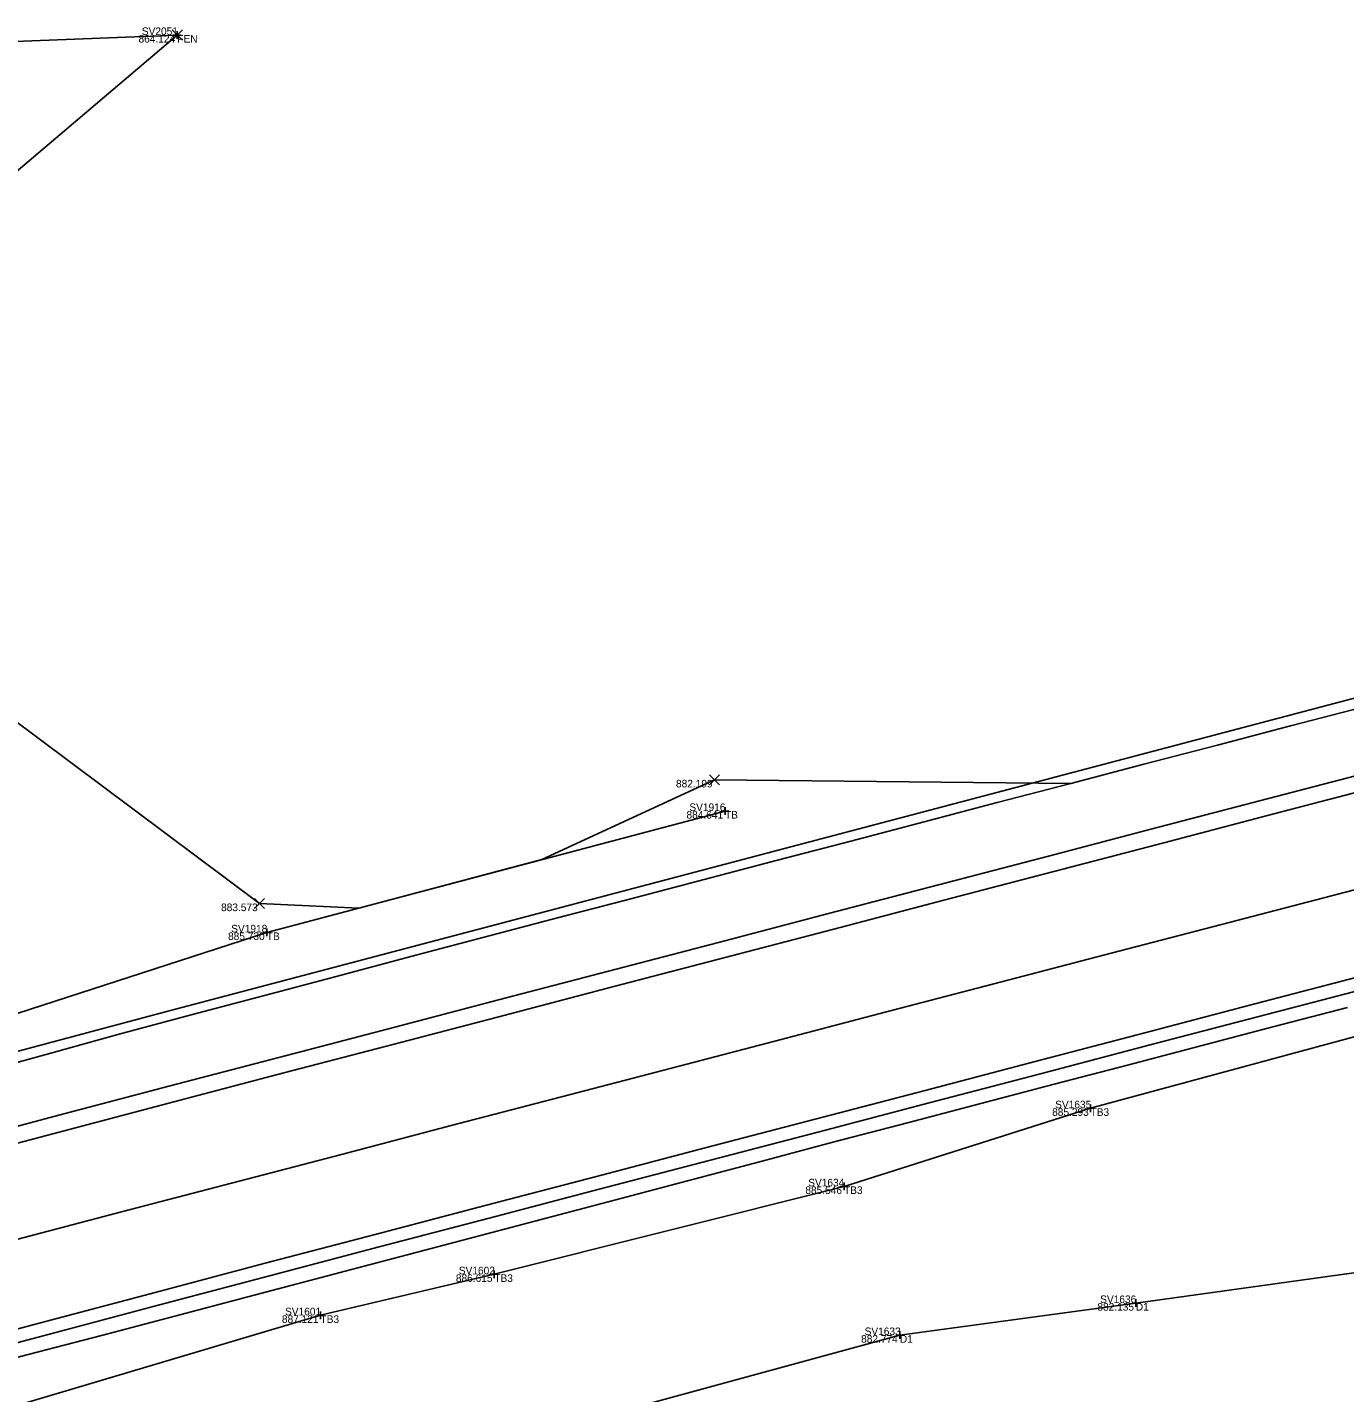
# Model space of a CAD drawing. Extents: x 2125299 to 2129212, y 713100 to 714300.
# Drawn here: x 2127665 to 2127838.8, y 713888.4 to 714068.6 of the extents above; entities that cross this region are included whole.
import ezdxf

# ---------------------------------------------------------------- set-up
doc = ezdxf.new("R2010")
doc.units = 0
for name, color, linetype in [('_CIVIL_CONSTRUCTION', 7, 'Continuous'), ('DR_X_Ditch', 7, 'Continuous'), ('DT_X_Terrain_Boundary', 7, 'Continuous'), ('PV_X_EOP', 7, 'Continuous'), ('PV_X_Shoulder_Rumble_Strip', 7, 'Continuous'), ('RD_X_Fence', 7, 'Continuous'), ('RW_P_Esmt_TMP', 7, 'Continuous'), ('RW_X_Esmt_CH', 7, 'Continuous'), ('RW_X_Fee_WL', 7, 'Continuous'), ('SC_Scratch1', 7, 'Continuous'), ('SC_Scratch2', 7, 'Continuous'), ('SV_X_Mon_Cells_Found', 7, 'Continuous'), ('SV_X_Text_Elevation', 7, 'Continuous'), ('SV_X_Top_of_Bank', 7, 'Continuous')]:
    doc.layers.add(name, color=color, linetype=linetype)

msp = doc.modelspace()

# ---------------------------------------------------------------- linework, layer by layer
at = {"layer": '_CIVIL_CONSTRUCTION'}
msp.add_lwpolyline([(2127662.9, 713908.47), (2127677.41, 713912.28), (2127691.92, 713916.07), (2127706.43, 713919.86), (2127720.94, 713923.65), (2127735.46, 713927.44), (2127749.97, 713931.24), (2127764.48, 713935.03), (2127779, 713938.82), (2127793.51, 713942.61), (2127808.02, 713946.4), (2127822.54, 713950.19), (2127837.05, 713953.98), (2127851.56, 713957.77)], dxfattribs=at)
at = {"layer": 'DR_X_Ditch'}
msp.add_lwpolyline([(2127104.46, 713722.2), (2127161.17, 713739.36), (2127224.94, 713755.07), (2127279.95, 713770.84), (2127341.71, 713787.57), (2127396.23, 713800.84), (2127459.54, 713814.71), (2127515.88, 713829.56), (2127633.42, 713858.63), (2127660.82, 713865.77), (2127680.17, 713870.09), (2127707.74, 713876.68), (2127734.62, 713883.6), (2127780.13, 713896.01), (2127811.25, 713900.24), (2127854.87, 713906.28), (2127890.1, 713912.55), (2127900.96, 713914.65)], dxfattribs=at)
at = {"layer": 'DT_X_Terrain_Boundary'}
for points in [[(2127631.15, 714022.04), (2127684.79, 714067.54), (2127637.39, 714065.66)], [(2127841.36, 713978.9), (2127831.68, 713976.38), (2127822.01, 713973.85), (2127812.33, 713971.32), (2127802.66, 713968.8), (2127755.66, 713969.27), (2127732.89, 713958.76), (2127708.73, 713952.35), (2127695.62, 713952.95), (2127637.63, 713996.27)]]:
    msp.add_lwpolyline(points, dxfattribs=at)
at = {"layer": 'PV_X_EOP'}
for points in [[(2127657.66, 713930.36), (2127667.31, 713933.01), (2127676.95, 713935.66), (2127686.6, 713938.27), (2127696.27, 713940.83), (2127705.94, 713943.39), (2127715.61, 713945.95), (2127725.27, 713948.5), (2127734.94, 713951.05), (2127744.62, 713953.58), (2127754.29, 713956.12), (2127763.96, 713958.66), (2127773.64, 713961.19), (2127783.31, 713963.73), (2127792.98, 713966.27), (2127802.66, 713968.8), (2127812.33, 713971.32), (2127822.01, 713973.85), (2127831.68, 713976.38), (2127841.36, 713978.9)], [(2127655.42, 713890.89), (2127665.1, 713893.44), (2127674.77, 713895.98), (2127684.44, 713898.52), (2127694.11, 713901.07), (2127703.78, 713903.61), (2127713.45, 713906.15), (2127723.12, 713908.7), (2127732.79, 713911.26), (2127742.46, 713913.82), (2127752.12, 713916.37), (2127761.79, 713918.93), (2127771.46, 713921.49), (2127781.13, 713924.03), (2127790.8, 713926.57), (2127800.48, 713929.11), (2127810.15, 713931.64), (2127819.82, 713934.18), (2127829.49, 713936.72), (2127839.17, 713939.25)]]:
    msp.add_lwpolyline(points, dxfattribs=at)
at = {"layer": 'PV_X_Shoulder_Rumble_Strip'}
for points in [[(2127654.66, 713921.17), (2127669.16, 713925.01), (2127683.66, 713928.84), (2127698.17, 713932.65), (2127712.67, 713936.44), (2127727.18, 713940.24), (2127741.69, 713944.04), (2127756.2, 713947.83), (2127770.71, 713951.63), (2127785.22, 713955.43), (2127799.73, 713959.22), (2127814.23, 713963.02), (2127828.74, 713966.81), (2127843.25, 713970.61), (2127857.76, 713974.41), (2127872.26, 713978.2), (2127886.77, 713982), (2127901.28, 713985.8), (2127915.79, 713989.59), (2127930.3, 713993.39), (2127944.81, 713997.19), (2127959.31, 714000.98), (2127973.82, 714004.78), (2127983.03, 714007.2)], [(2127653.45, 713892.3), (2127667.94, 713896.15), (2127682.44, 713899.99), (2127696.93, 713903.84), (2127711.44, 713907.65), (2127725.95, 713911.45), (2127740.46, 713915.25), (2127754.96, 713919.05), (2127769.47, 713922.85), (2127783.98, 713926.65), (2127798.49, 713930.45), (2127812.99, 713934.25), (2127827.5, 713938.05), (2127842.01, 713941.85), (2127856.51, 713945.65), (2127871.02, 713949.45), (2127885.53, 713953.25), (2127900.03, 713957.05), (2127914.54, 713960.85), (2127929.05, 713964.65), (2127943.56, 713968.45), (2127958.06, 713972.25), (2127972.57, 713976.05), (2127975.95, 713976.94)]]:
    msp.add_lwpolyline(points, dxfattribs=at)
at = {"layer": 'RD_X_Fence'}
msp.add_lwpolyline([(2127684.79, 714067.54), (2127637.39, 714065.66), (2127578.97, 714061.9), (2127530.03, 714058.91), (2127501.39, 714057.24), (2127432.97, 714052.74), (2127408.21, 714050.18), (2127386.8, 714040.45)], dxfattribs=at)
at = {"layer": 'SC_Scratch1'}
msp.add_lwpolyline([(2127987.17, 714018.86), (2127920.93, 714001.38), (2127683.07, 713938.63), (2127539.5, 713900.27), (2127439.69, 713873.74), (2127381.79, 713858.41), (2127328.47, 713844.31), (2127152.7, 713796.25), (2127072.88, 713773.07)], dxfattribs=at)
at = {"layer": 'SC_Scratch2'}
for points in [[(2127655.35, 713919.13), (2127669.85, 713922.96), (2127684.35, 713926.8), (2127698.86, 713930.6), (2127713.38, 713934.4), (2127727.89, 713938.2), (2127742.4, 713941.99), (2127756.91, 713945.79), (2127771.42, 713949.59), (2127785.93, 713953.39), (2127800.44, 713957.18), (2127814.96, 713960.98), (2127829.47, 713964.78), (2127843.98, 713968.57)], [(2127652.88, 713893.95), (2127667.38, 713897.79), (2127681.88, 713901.64), (2127696.38, 713905.49), (2127710.89, 713909.3), (2127725.4, 713913.1), (2127739.91, 713916.9), (2127754.42, 713920.7), (2127768.93, 713924.5), (2127783.44, 713928.3), (2127797.95, 713932.1), (2127812.46, 713935.9), (2127826.97, 713939.7), (2127841.48, 713943.5)]]:
    msp.add_lwpolyline(points, dxfattribs=at)
at = {"layer": 'SV_X_Mon_Cells_Found'}
for p, q in [((2127684.29, 714067.54), (2127685.29, 714067.54)), ((2127684.79, 714068.04), (2127684.79, 714067.04)), ((2127684.79, 714067.54), (2127684.79, 714067.54)), ((2127756.55, 713965.16), (2127757.55, 713965.16)), ((2127757.05, 713965.66), (2127757.05, 713964.66)), ((2127757.05, 713965.16), (2127757.05, 713965.16)), ((2127696.1, 713949.14), (2127697.1, 713949.14)), ((2127696.6, 713949.64), (2127696.6, 713948.64)), ((2127696.6, 713949.14), (2127696.6, 713949.14)), ((2127804.78, 713925.94), (2127805.78, 713925.94)), ((2127805.28, 713926.44), (2127805.28, 713925.44)), ((2127805.28, 713925.94), (2127805.28, 713925.94)), ((2127772.25, 713915.63), (2127773.25, 713915.63)), ((2127772.75, 713916.13), (2127772.75, 713915.13)), ((2127772.75, 713915.63), (2127772.75, 713915.63)), ((2127726.11, 713904.03), (2127727.11, 713904.03)), ((2127726.61, 713904.53), (2127726.61, 713903.53)), ((2127726.61, 713904.03), (2127726.61, 713904.03)), ((2127810.75, 713900.24), (2127811.75, 713900.24)), ((2127811.25, 713900.74), (2127811.25, 713899.74)), ((2127811.25, 713900.24), (2127811.25, 713900.24)), ((2127703.18, 713898.62), (2127704.18, 713898.62)), ((2127703.68, 713899.12), (2127703.68, 713898.12)), ((2127703.68, 713898.62), (2127703.68, 713898.62)), ((2127780.13, 713896.51), (2127780.13, 713895.51)), ((2127779.63, 713896.01), (2127780.63, 713896.01)), ((2127780.13, 713896.01), (2127780.13, 713896.01))]:
    msp.add_line(p, q, dxfattribs=at)
at = {"layer": 'SV_X_Text_Elevation'}
for p, q in [((2127684.13, 714066.88), (2127685.46, 714068.21)), ((2127684.13, 714068.21), (2127685.46, 714066.88)), ((2127755, 713968.6), (2127756.33, 713969.93)), ((2127755, 713969.93), (2127756.33, 713968.6)), ((2127694.96, 713952.28), (2127696.29, 713953.62)), ((2127694.96, 713953.62), (2127696.29, 713952.28))]:
    msp.add_line(p, q, dxfattribs=at)
at = {"layer": 'SV_X_Top_of_Bank'}
for points in [[(2127101.4, 713732.92), (2127157.86, 713749.53), (2127222.47, 713767.6), (2127276.61, 713783.01), (2127338.05, 713802.99), (2127391.69, 713816.17), (2127455.85, 713833.15), (2127455.8, 713833.25), (2127510.11, 713848.18), (2127573.33, 713861.42), (2127627.49, 713877.76), (2127656.95, 713884.76), (2127703.68, 713898.62), (2127726.61, 713904.03), (2127772.75, 713915.63), (2127805.28, 713925.94), (2127847.55, 713937.37), (2127886.63, 713945.55), (2127933.44, 713957.72), (2127971.8, 713964.93)], [(2127757.05, 713965.16), (2127696.6, 713949.14), (2127640.68, 713931.02), (2127581.66, 713919.2), (2127522.16, 713901.86), (2127455.22, 713885.36), (2127396.67, 713869.65)]]:
    msp.add_lwpolyline(points, dxfattribs=at)

# ---------------------------------------------------------------- texts
at = {"layer": 'RW_P_Esmt_TMP'}
for s, p in [('FEN', (2127684.79, 714066.54)), ('TB', (2127757.05, 713964.16)), ('TB', (2127696.6, 713948.14)), ('TB3', (2127805.28, 713924.94)), ('TB3', (2127772.75, 713914.63)), ('TB3', (2127726.61, 713903.03)), ('D1', (2127811.25, 713899.24)), ('TB3', (2127703.68, 713897.62)), ('D1', (2127780.13, 713895.01))]:
    msp.add_text(s, height=1, dxfattribs=at).set_placement(p)
at = {"layer": 'RW_X_Esmt_CH'}
for s, p in [('SV2051', (2127680.11, 714067.54)), ('SV1916', (2127752.35, 713965.16)), ('SV1918', (2127691.9, 713949.14)), ('SV1635', (2127800.61, 713925.94)), ('SV1634', (2127768.03, 713915.63)), ('SV1602', (2127721.93, 713904.03)), ('SV1636', (2127806.55, 713900.24)), ('SV1601', (2127699, 713898.62)), ('SV1633', (2127775.47, 713896.01))]:
    msp.add_text(s, height=1, dxfattribs=at).set_placement(p)
at = {"layer": 'RW_X_Fee_WL'}
for s, p in [('864.124', (2127679.67, 714066.54)), ('864.124', (2127679.67, 714066.54)), ('882.199', (2127750.58, 713968.27)), ('884.641', (2127751.97, 713964.16)), ('883.573', (2127690.56, 713951.95)), ('885.730', (2127691.48, 713948.14)), ('885.293', (2127800.21, 713924.94)), ('885.546', (2127767.65, 713914.63)), ('886.615', (2127721.54, 713903.03)), ('882.135', (2127806.18, 713899.24)), ('887.121', (2127698.59, 713897.62)), ('882.774', (2127775.01, 713895.01))]:
    msp.add_text(s, height=1, dxfattribs=at).set_placement(p)

doc.saveas('drawing.dxf')
